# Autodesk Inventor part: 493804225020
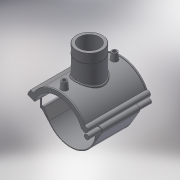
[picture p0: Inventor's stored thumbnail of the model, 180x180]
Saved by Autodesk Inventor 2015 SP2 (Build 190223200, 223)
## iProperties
Created: 2017-07
Part Number: 493804225020
Material: Generic
Description: PLASSON TRANSITION SADDLE 225-2"
Document SubType Name: Modeling
Designer: KIM
Density: 1 g/cm^3
Appearance: Default
Author: KIM
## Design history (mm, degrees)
derived "493804.ipt"
feature "Solid1::493804.ipt"
tag "TaggingFeature1"
body "Solid1"
other parameters: "d_" = 225, "B_" = 227, "H_" = 76, "L_" = 176, "d_t" = 6, "G_" = 56.656, "d148" = 3.375, "d160" = 3.375, "d169" = 3.375, "d192" = 6.75, "d0" = 225, "d1" = 258.75, "d2" = 295.1, "d3" = 56.25, "d4" = 176, "d5" = 0, "d6" = 0.1, "d8" = 0, "d19" = 6, "d20" = 6, "d21" = 105.6, "d23" = 0, "d24" = 52.8, "d26" = 0, "d27" = 3, "d28" = 3, "d29" = 3, "d30" = 75, "d31" = 6, "d32" = 0, "d33" = 0, "d34" = 0.6, "d40" = 134.55, "d41" = 79.3184, "d43" = 0, "d45" = 0, "d47" = 205.375, "d48" = 73.6528, "d50" = 0, "d70" = 15, "d72" = 0, "d73" = 6, "d75" = 5, "d76" = 0, "d77" = 11.25, "d78" = 142.5, "d79" = 15, "d80" = 70.4, "d82" = 5 deg, "d84" = 4, "d85" = 14, "d86" = 0, "d87" = 3, "d88" = 0, "d89" = 1, "d90" = 1, "d91" = 140.8, "d92" = 0, "d93" = 0.5, "d94" = 118.42105, "d96" = 263.925, "d97" = 3.52, "d98" = 0, "d102" = 1.69968, "d103" = 56.656, "d104" = 45.6, "d105" = 0, "d106" = 45.3248, "d108" = 0, "d109" = -25.33333, "d111" = 0.5, "d112" = 0.5, "d113" = 0, "d114" = 0.5, "d117" = 0.56656, "d120" = 140 deg, "d121" = 24.228, "d122" = 20 deg, "d123" = 517.5, "d124" = 155.25, "d126" = 0, "d143" = 231.75, "d145" = 25.96154, "d149" = 3.375, "d150" = 28.55769, "d153" = 176, "d154" = 0, "d156" = 129.375, "d157" = 160 deg, "d159" = 6.75, "d161" = 3.375, "d162" = 105.6, "d163" = 0, "d164" = 112.5, "d167" = 22.5, "d168" = 126.21951, "d170" = 3.375, "d172" = 0, "d173" = 1, "d175" = 112.5, "d176" = 20 deg, "d177" = 15.75, "d178" = 33.75, "d180" = 0, "d183" = 13.5, "d184" = 12.6, "d185" = 57.2, "d186" = 57.2, "d187" = 129.375, "d188" = 10.125, "d189" = 15.75, "d190" = 0, "d191" = 155.25, "d193" = 6.75, "d194" = 4.4, "d195" = 90 deg, "d197" = 0, "d199" = 0
